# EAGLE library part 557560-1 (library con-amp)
AMP connector
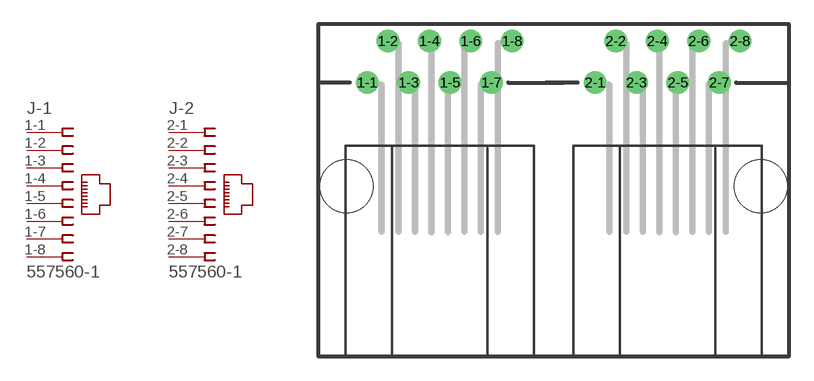
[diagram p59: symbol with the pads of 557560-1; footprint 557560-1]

Designator prefix J; gates -1=JACK8 -2=JACK8

## 557560-1 (MPN: 5557560-1; OC_FARNELL: 1336595; OC_NEWARK: 16M4013)  [557560-1]
1-1  -1:1  pas
1-2  -1:2  pas
1-3  -1:3  pas
1-4  -1:4  pas
1-5  -1:5  pas
1-6  -1:6  pas
1-7  -1:7  pas
1-8  -1:8  pas
2-1  -2:1  pas
2-2  -2:2  pas
2-3  -2:3  pas
2-4  -2:4  pas
2-5  -2:5  pas
2-6  -2:6  pas
2-7  -2:7  pas
2-8  -2:8  pas

## Footprint 557560-1 (pad centres in mm)
Modular Jack
drill 0.889 round: 1-1 -11.43,6.35; 1-2 -10.16,8.89; 1-3 -8.89,6.35; 1-4 -7.62,8.89; 1-5 -6.35,6.35; 1-6 -5.08,8.89; 1-7 -3.81,6.35; 1-8 -2.54,8.89; 2-1 2.54,6.35; 2-2 3.81,8.89; 2-3 5.08,6.35; 2-4 6.35,8.89; 2-5 7.62,6.35; 2-6 8.89,8.89; 2-7 10.16,6.35; 2-8 11.43,8.89
hole 3.251 at -12.7,0
hole 3.251 at 12.7,0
